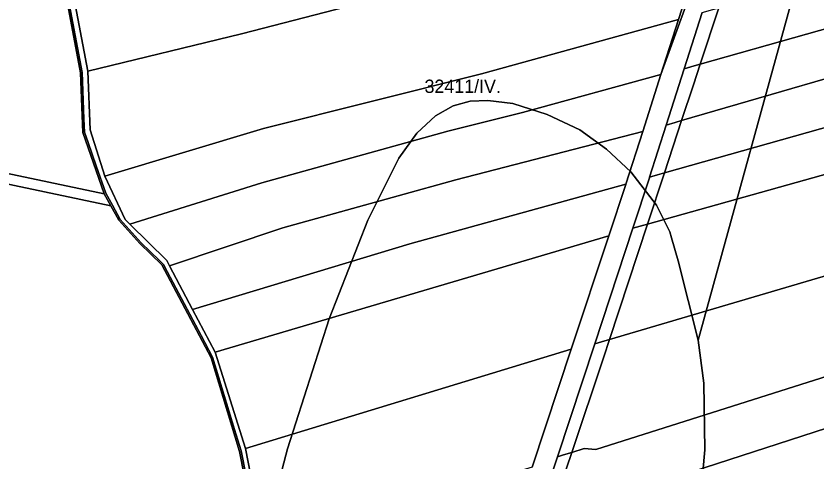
# Model space of a CAD drawing. Extents: x -535894 to -532834, y -1165802 to -1163645.
# Drawn here: x -534170.3 to -533869.9, y -1164187.8 to -1164020.6 of the extents above; entities that cross this region are included whole.
import ezdxf

# ---------------------------------------------------------------- set-up
doc = ezdxf.new("R2010")
doc.units = 0
for name, color, linetype in [('95560013', 7, 'Continuous'), ('95620013', 7, 'Continuous'), ('95640013', 7, 'Continuous'), ('95660013', 7, 'Continuous')]:
    doc.layers.add(name, color=color, linetype=linetype)

msp = doc.modelspace()

# ---------------------------------------------------------------- linework, layer by layer
at = {"layer": '95560013'}
for points in [[(-533895.7, -1163940.37), (-533908.87, -1163981.51), (-534085.67, -1164027.32), (-534143.34, -1164041.3), (-534150.32, -1164004.31), (-533932.68, -1163949.92)], [(-533921.81, -1164021.92), (-533995.77, -1164042.33), (-534077.52, -1164062.7), (-534136.93, -1164080.66), (-534142.42, -1164063.29), (-534143.34, -1164041.3), (-534085.67, -1164027.32), (-533908.87, -1163981.51)], [(-533836.92, -1164005.27), (-533833.99, -1164016.17), (-533913.66, -1164038.64), (-533906.69, -1164017.55), (-533879.17, -1164009.99), (-533838.01, -1164000.05)], [(-533829.37, -1164033.3), (-533920.66, -1164059.82), (-533916.23, -1164046.38), (-533913.66, -1164038.64), (-533833.99, -1164016.17)], [(-533995.77, -1164042.33), (-533921.81, -1164021.92), (-533928.41, -1164042.51), (-533980.32, -1164056.75), (-534008.3, -1164063.7), (-534078.07, -1164083.07), (-534127.6, -1164098.58), (-534129.39, -1164096.82), (-534136.93, -1164080.66), (-534077.52, -1164062.7)], [(-533824.72, -1164050.56), (-533927.12, -1164079.43), (-533920.66, -1164059.82), (-533829.37, -1164033.3)], [(-533980.32, -1164056.75), (-533928.41, -1164042.51), (-533935.24, -1164063.87), (-534005.35, -1164082), (-534070.18, -1164099.94), (-534112.65, -1164114.3), (-534113.76, -1164112.22), (-534127.6, -1164098.58), (-534078.07, -1164083.07), (-534008.3, -1164063.7)], [(-533823.91, -1164053.54), (-533818.83, -1164066.55), (-533933.43, -1164098.59), (-533927.12, -1164079.43), (-533824.72, -1164050.56)], [(-534005.35, -1164082), (-533935.24, -1164063.87), (-533941.57, -1164083.63), (-534022.58, -1164105.96), (-534104.05, -1164130.62), (-534112.65, -1164114.3), (-534070.18, -1164099.94)], [(-533933.43, -1164098.59), (-533818.83, -1164066.55), (-533805.75, -1164099.98), (-533947.71, -1164141.88)], [(-533941.6, -1164083.7), (-533947.99, -1164103.02), (-534095.57, -1164146.67), (-534104.05, -1164130.62), (-534022.58, -1164105.96), (-533941.57, -1164083.63)], [(-533803.18, -1164106.57), (-533791.66, -1164132.02), (-533952.85, -1164183.05), (-533957.22, -1164182.74), (-533961.89, -1164184.21), (-533949.83, -1164148.31), (-533947.71, -1164141.88), (-533805.75, -1164099.98)], [(-533962.05, -1164145.52), (-534084.16, -1164182.76), (-534095.57, -1164146.67), (-533947.99, -1164103.02)], [(-533787.38, -1164141.47), (-533783.44, -1164148.24), (-533944.24, -1164200.35), (-533969.8, -1164207.76), (-533961.89, -1164184.21), (-533957.22, -1164182.74), (-533952.85, -1164183.05), (-533791.66, -1164132.02)], [(-534084.16, -1164182.76), (-533962.05, -1164145.52), (-533976.56, -1164189.37), (-533976.67, -1164189.68), (-534076.92, -1164219.96)], [(-533774.86, -1164162.96), (-533792.93, -1164169.52), (-533834.65, -1164183.03), (-533919.48, -1164212.04), (-533965.3, -1164226.17), (-533968.9, -1164225.77), (-533976.69, -1164228.26), (-533969.8, -1164207.76), (-533944.24, -1164200.35), (-533783.44, -1164148.24)]]:
    msp.add_lwpolyline(points, close=True, dxfattribs=at)
at = {"layer": '95620013'}
msp.add_lwpolyline([(-534576.69, -1163994.7), (-534428.93, -1164025.8), (-534431.31, -1163750.05), (-534427.72, -1163752.13), (-534425.41, -1164026.54), (-534137.15, -1164087.2), (-534134.69, -1164091.75), (-534426.2, -1164030.27), (-534422.39, -1164273.15), (-534424.3, -1164273.92), (-534426.3, -1164271.96), (-534429.37, -1164029.61), (-534577.82, -1163998.3)], dxfattribs=at)
for points in [[(-534427.72, -1163752.13), (-534413.24, -1163763.36), (-534362.72, -1163807.37), (-534355.93, -1163819.24), (-534338.84, -1163838.27), (-534314.16, -1163855.97), (-534296.47, -1163870.97), (-534271.49, -1163905.38), (-534250.57, -1163903.14), (-534241.76, -1163894.34), (-534224.22, -1163957.18), (-534156.41, -1163945.04), (-534157.94, -1163978.43), (-534146.05, -1164041.92), (-534145.18, -1164064.32), (-534137.15, -1164087.2), (-534425.41, -1164026.54)], [(-534426.2, -1164030.27), (-534134.69, -1164091.75), (-534131.77, -1164097.12), (-534123.86, -1164105.89), (-534115.56, -1164113.93), (-534097.11, -1164148.68), (-534086.47, -1164183.86), (-534079.09, -1164221.21), (-534079.7, -1164259.55), (-534075.33, -1164283.15), (-534074.04, -1164285.93), (-534144.82, -1164304.74), (-534177.29, -1164303.6), (-534197.87, -1164299.21), (-534274.99, -1164277.69), (-534335.13, -1164267.45), (-534369.81, -1164273.2), (-534388.51, -1164274.7), (-534418.8, -1164271.7), (-534422.39, -1164273.15)]]:
    msp.add_lwpolyline(points, close=True, dxfattribs=at)
at = {"layer": '95640013'}
for points in [[(-533892.46, -1163911.51), (-533891.45, -1163899.11), (-533890.48, -1163923.29), (-533892.48, -1163938), (-533897.78, -1163957.92), (-533928.41, -1164042.51), (-533921.81, -1164021.92), (-533908.87, -1163981.51), (-533895.7, -1163940.37), (-533894.49, -1163936.59), (-533893.61, -1163925.64)], [(-533908.91, -1164018.16), (-533906.69, -1164017.55), (-533913.66, -1164038.64), (-533915.99, -1164039.3), (-533919.67, -1164040.34), (-533912.94, -1164019.27)], [(-533915.99, -1164039.3), (-533913.66, -1164038.64), (-533916.23, -1164046.38), (-533920.66, -1164059.82), (-533923.11, -1164060.54), (-533926.43, -1164061.51), (-533919.67, -1164040.34)], [(-533923.11, -1164060.54), (-533920.66, -1164059.82), (-533927.12, -1164079.43), (-533929.71, -1164080.17), (-533932.66, -1164081), (-533926.43, -1164061.51)], [(-533929.71, -1164080.17), (-533927.12, -1164079.43), (-533933.43, -1164098.59), (-533936.16, -1164099.35), (-533938.96, -1164100.13), (-533932.74, -1164081.26), (-533932.66, -1164081)], [(-533936.16, -1164099.35), (-533933.43, -1164098.59), (-533947.71, -1164141.88), (-533950.75, -1164142.78), (-533953.25, -1164143.52), (-533938.96, -1164100.13)], [(-533950.75, -1164142.78), (-533947.71, -1164141.88), (-533949.83, -1164148.31), (-533961.89, -1164184.21), (-533964.91, -1164185.16), (-533967.21, -1164185.88), (-533953.25, -1164143.52)], [(-533964.91, -1164185.16), (-533961.89, -1164184.21), (-533969.8, -1164207.76), (-533972.74, -1164208.61), (-533974.91, -1164209.24), (-533967.21, -1164185.88)]]:
    msp.add_lwpolyline(points, close=True, dxfattribs=at)
for points in [[(-533976.56, -1164189.37), (-533962.05, -1164145.52), (-533947.99, -1164103.02), (-533941.6, -1164083.7), (-533941.57, -1164083.63), (-533935.24, -1164063.87), (-533928.41, -1164042.51), (-533897.78, -1163957.92)], [(-534079.09, -1164221.21), (-534086.47, -1164183.86), (-534097.11, -1164148.68), (-534115.56, -1164113.93), (-534123.86, -1164105.89), (-534131.77, -1164097.12), (-534134.69, -1164091.75), (-534137.15, -1164087.2), (-534145.18, -1164064.32), (-534146.05, -1164041.92), (-534157.94, -1163978.43)], [(-534150.32, -1164004.31), (-534143.34, -1164041.3), (-534142.42, -1164063.29), (-534136.93, -1164080.66), (-534129.39, -1164096.82), (-534127.6, -1164098.58), (-534113.76, -1164112.22), (-534112.65, -1164114.3), (-534104.05, -1164130.62), (-534095.57, -1164146.67), (-534084.16, -1164182.76), (-534076.92, -1164219.96)], [(-533912.94, -1164019.27), (-533919.67, -1164040.34), (-533926.43, -1164061.51), (-533932.66, -1164081), (-533932.74, -1164081.26), (-533938.96, -1164100.13), (-533953.25, -1164143.52), (-533967.21, -1164185.88), (-533974.91, -1164209.24)]]:
    msp.add_lwpolyline(points, dxfattribs=at)
at = {"layer": '95660013'}
for points in [[(-533875.366, -1164000), (-533914.47, -1164142.17), (-533921.943, -1164112.324), (-533924.425, -1164103.745), (-533925.06, -1164101.55), (-533930.08, -1164091.52), (-533939.763, -1164078.96), (-533948.79, -1164070.49), (-533958.872, -1164063.308), (-533971.09, -1164057.51), (-533983.99, -1164053.45), (-533993.341, -1164052.28), (-533999.92, -1164052.57), (-534006.29, -1164054.239), (-534012.98, -1164057.99), (-534019.91, -1164064.519), (-534026.76, -1164073.91), (-534038.39, -1164097.17), (-534052.88, -1164134.121), (-534068.49, -1164182.86), (-534078.523, -1164221.003), (-534085.899, -1164183.652), (-534088.342, -1164175.577), (-534095.182, -1164152.964), (-534096.544, -1164148.462), (-534100.815, -1164140.418), (-534113.603, -1164116.335), (-534114.995, -1164113.714), (-534116.451, -1164112.304), (-534123.297, -1164105.677), (-534131.206, -1164096.91), (-534134.129, -1164091.534), (-534136.591, -1164086.985), (-534140.179, -1164076.764), (-534143.251, -1164068.015), (-534144.622, -1164064.109), (-534144.816, -1164059.106), (-534145.49, -1164041.708), (-534153.303, -1164000)], [(-534153.303, -1164000), (-534145.49, -1164041.708), (-534144.816, -1164059.106), (-534144.622, -1164064.109), (-534143.251, -1164068.015), (-534140.179, -1164076.764), (-534136.591, -1164086.985), (-534134.129, -1164091.534), (-534131.206, -1164096.91), (-534123.297, -1164105.677), (-534116.451, -1164112.304), (-534114.995, -1164113.714), (-534113.603, -1164116.335), (-534100.815, -1164140.418), (-534096.544, -1164148.462), (-534095.182, -1164152.964), (-534088.342, -1164175.577), (-534085.899, -1164183.652), (-534078.523, -1164221.003)], [(-533912.751, -1164191.59), (-533911.92, -1164183.18), (-533912.32, -1164158.25), (-533914.47, -1164142.17), (-533875.366, -1164000)], [(-534078.523, -1164221.003), (-534068.49, -1164182.86), (-534052.88, -1164134.121), (-534038.39, -1164097.17), (-534026.76, -1164073.91), (-534019.91, -1164064.519), (-534012.98, -1164057.99), (-534006.29, -1164054.239), (-533999.92, -1164052.57), (-533993.341, -1164052.28), (-533983.99, -1164053.45), (-533971.09, -1164057.51), (-533958.872, -1164063.308), (-533948.79, -1164070.49), (-533939.763, -1164078.96), (-533930.08, -1164091.52), (-533925.06, -1164101.55), (-533924.425, -1164103.745), (-533921.943, -1164112.324), (-533914.47, -1164142.17), (-533912.32, -1164158.25), (-533911.92, -1164183.18), (-533912.751, -1164191.59)]]:
    msp.add_lwpolyline(points, dxfattribs=at)

# ---------------------------------------------------------------- texts
msp.add_text('32411/IV.', height=5, rotation=360, dxfattribs=at).set_placement((-534017.076, -1164049.432))

doc.saveas('drawing.dxf')
